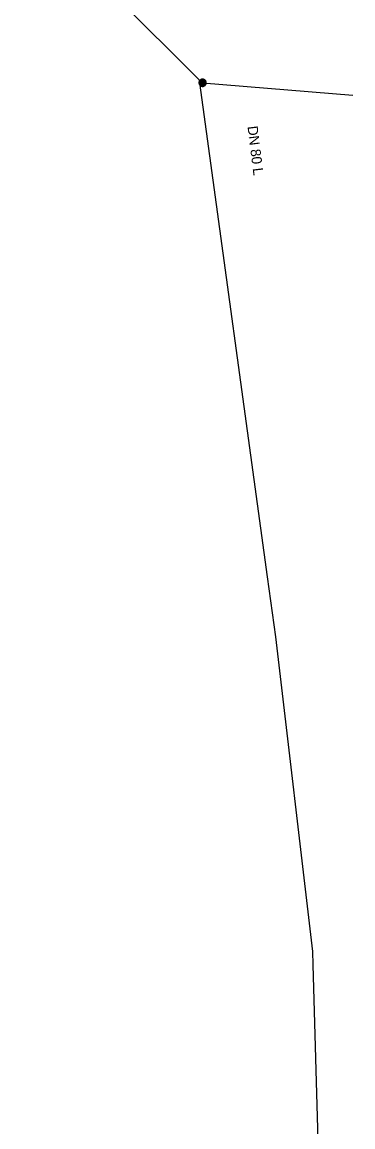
# Model space of a CAD drawing. Extents: x -818321 to -817653, y -1049725 to -1049329.
# Drawn here: x -818104.3 to -818081.5, y -1049527 to -1049450.7 of the extents above; entities that cross this region are included whole.
import ezdxf

# ---------------------------------------------------------------- set-up
doc = ezdxf.new("R2010")
doc.units = 0
doc.layers.add('Default', color=7, linetype='Continuous')
doc.layers.add('Level 0', color=7, linetype='Continuous')

msp = doc.modelspace()

# ---------------------------------------------------------------- linework, layer by layer
at = {"layer": 'Default'}
for points in [[(-818091.895, -1049454.663), (-818091.832, -1049454.663), (-818091.773, -1049454.695), (-818091.713, -1049454.727), (-818091.679, -1049454.787), (-818091.645, -1049454.848), (-818091.645, -1049454.913), (-818091.645, -1049454.978), (-818091.678, -1049455.037), (-818091.711, -1049455.097), (-818091.771, -1049455.13), (-818091.83, -1049455.163), (-818091.895, -1049455.163), (-818091.96, -1049455.163), (-818092.02, -1049455.13), (-818092.079, -1049455.097), (-818092.112, -1049455.037), (-818092.145, -1049454.978), (-818092.145, -1049454.913), (-818092.145, -1049454.848), (-818092.112, -1049454.787), (-818092.078, -1049454.727), (-818092.018, -1049454.695), (-818091.959, -1049454.663), (-818091.895, -1049454.663)], [(-818091.895, -1049454.686), (-818091.953, -1049454.686), (-818092.007, -1049454.715), (-818092.061, -1049454.745), (-818092.091, -1049454.799), (-818092.122, -1049454.854), (-818092.122, -1049454.913), (-818092.122, -1049454.972), (-818092.092, -1049455.026), (-818092.062, -1049455.08), (-818092.008, -1049455.11), (-818091.954, -1049455.139), (-818091.895, -1049455.139), (-818091.836, -1049455.139), (-818091.782, -1049455.11), (-818091.728, -1049455.08), (-818091.698, -1049455.026), (-818091.669, -1049454.972), (-818091.669, -1049454.913), (-818091.669, -1049454.854), (-818091.699, -1049454.799), (-818091.73, -1049454.745), (-818091.784, -1049454.715), (-818091.838, -1049454.686), (-818091.895, -1049454.686)], [(-818091.895, -1049454.703), (-818091.842, -1049454.703), (-818091.793, -1049454.73), (-818091.743, -1049454.757), (-818091.714, -1049454.808), (-818091.686, -1049454.858), (-818091.686, -1049454.913), (-818091.686, -1049454.968), (-818091.713, -1049455.017), (-818091.741, -1049455.067), (-818091.791, -1049455.095), (-818091.841, -1049455.122), (-818091.895, -1049455.122), (-818091.95, -1049455.122), (-818092, -1049455.095), (-818092.05, -1049455.067), (-818092.077, -1049455.017), (-818092.105, -1049454.968), (-818092.105, -1049454.913), (-818092.105, -1049454.858), (-818092.077, -1049454.808), (-818092.049, -1049454.757), (-818091.998, -1049454.73), (-818091.948, -1049454.703), (-818091.895, -1049454.703)], [(-818091.896, -1049454.725), (-818091.974, -1049454.725), (-818092.028, -1049454.78), (-818092.083, -1049454.835), (-818092.083, -1049454.913), (-818092.083, -1049454.991), (-818092.028, -1049455.046), (-818091.973, -1049455.1), (-818091.896, -1049455.1), (-818091.818, -1049455.1), (-818091.763, -1049455.046), (-818091.708, -1049454.991), (-818091.708, -1049454.913), (-818091.708, -1049454.835), (-818091.762, -1049454.78), (-818091.817, -1049454.725), (-818091.896, -1049454.725)], [(-818091.896, -1049454.748), (-818091.827, -1049454.748), (-818091.779, -1049454.796), (-818091.732, -1049454.844), (-818091.732, -1049454.912), (-818091.732, -1049454.98), (-818091.78, -1049455.028), (-818091.828, -1049455.076), (-818091.896, -1049455.076), (-818091.964, -1049455.076), (-818092.012, -1049455.028), (-818092.06, -1049454.98), (-818092.06, -1049454.912), (-818092.06, -1049454.844), (-818092.012, -1049454.796), (-818091.964, -1049454.748), (-818091.896, -1049454.748)], [(-818091.896, -1049454.768), (-818091.956, -1049454.768), (-818091.998, -1049454.81), (-818092.04, -1049454.853), (-818092.04, -1049454.912), (-818092.04, -1049454.972), (-818091.998, -1049455.014), (-818091.956, -1049455.057), (-818091.896, -1049455.057), (-818091.836, -1049455.057), (-818091.794, -1049455.014), (-818091.751, -1049454.972), (-818091.751, -1049454.912), (-818091.751, -1049454.853), (-818091.793, -1049454.81), (-818091.835, -1049454.768), (-818091.896, -1049454.768)], [(-818091.895, -1049454.788), (-818091.843, -1049454.788), (-818091.807, -1049454.824), (-818091.77, -1049454.861), (-818091.77, -1049454.913), (-818091.77, -1049454.965), (-818091.807, -1049455.001), (-818091.843, -1049455.038), (-818091.895, -1049455.038), (-818091.947, -1049455.038), (-818091.984, -1049455.001), (-818092.02, -1049454.965), (-818092.02, -1049454.913), (-818092.02, -1049454.861), (-818091.984, -1049454.824), (-818091.948, -1049454.788), (-818091.895, -1049454.788)], [(-818091.895, -1049454.811), (-818091.938, -1049454.811), (-818091.967, -1049454.841), (-818091.997, -1049454.87), (-818091.997, -1049454.913), (-818091.997, -1049454.955), (-818091.967, -1049454.985), (-818091.938, -1049455.014), (-818091.895, -1049455.014), (-818091.853, -1049455.014), (-818091.824, -1049454.985), (-818091.794, -1049454.955), (-818091.794, -1049454.913), (-818091.794, -1049454.87), (-818091.824, -1049454.841), (-818091.853, -1049454.811), (-818091.895, -1049454.811)], [(-818091.895, -1049454.828), (-818091.86, -1049454.828), (-818091.836, -1049454.853), (-818091.811, -1049454.877), (-818091.811, -1049454.913), (-818091.811, -1049454.948), (-818091.836, -1049454.972), (-818091.861, -1049454.997), (-818091.895, -1049454.997), (-818091.931, -1049454.997), (-818091.955, -1049454.972), (-818091.98, -1049454.948), (-818091.98, -1049454.913), (-818091.98, -1049454.877), (-818091.955, -1049454.853), (-818091.931, -1049454.828), (-818091.895, -1049454.828)], [(-818091.895, -1049454.85), (-818091.921, -1049454.85), (-818091.94, -1049454.869), (-818091.958, -1049454.887), (-818091.958, -1049454.913), (-818091.958, -1049454.939), (-818091.939, -1049454.957), (-818091.921, -1049454.975), (-818091.895, -1049454.975), (-818091.869, -1049454.975), (-818091.851, -1049454.957), (-818091.833, -1049454.939), (-818091.833, -1049454.913), (-818091.833, -1049454.887), (-818091.851, -1049454.869), (-818091.869, -1049454.85), (-818091.895, -1049454.85)], [(-818091.895, -1049454.874), (-818091.879, -1049454.874), (-818091.868, -1049454.885), (-818091.856, -1049454.896), (-818091.856, -1049454.913), (-818091.856, -1049454.929), (-818091.868, -1049454.94), (-818091.879, -1049454.952), (-818091.895, -1049454.952), (-818091.912, -1049454.952), (-818091.923, -1049454.94), (-818091.935, -1049454.929), (-818091.935, -1049454.913), (-818091.935, -1049454.896), (-818091.923, -1049454.885), (-818091.912, -1049454.874), (-818091.895, -1049454.874)], [(-818091.895, -1049454.889), (-818091.905, -1049454.889), (-818091.912, -1049454.896), (-818091.919, -1049454.903), (-818091.919, -1049454.913), (-818091.919, -1049454.923), (-818091.912, -1049454.929), (-818091.905, -1049454.936), (-818091.895, -1049454.936), (-818091.885, -1049454.936), (-818091.879, -1049454.929), (-818091.872, -1049454.923), (-818091.872, -1049454.913), (-818091.872, -1049454.903), (-818091.879, -1049454.896), (-818091.885, -1049454.889), (-818091.895, -1049454.889)]]:
    msp.add_open_spline(points, degree=3, dxfattribs=at)
at = {"layer": 'Level 0'}
for p, q in [((-818104.333, -1049442.508), (-818092.141, -1049454.717)), ((-818092.141, -1049454.717), (-818092.119, -1049454.913)), ((-818092.119, -1049454.913), (-818087.437, -1049489.009)), ((-818092.119, -1049454.913), (-818091.895, -1049454.913)), ((-818091.895, -1049454.913), (-818081.538, -1049455.76)), ((-818087.437, -1049489.009), (-818086.868, -1049493.15)), ((-818086.868, -1049493.15), (-818084.324, -1049514.864)), ((-818084.324, -1049514.864), (-818084.297, -1049515.783)), ((-818084.297, -1049515.783), (-818083.68, -1049536.893))]:
    msp.add_line(p, q, dxfattribs=at)

# ---------------------------------------------------------------- texts
msp.add_text('DN 80 L', height=0.7, rotation=277, dxfattribs=at).set_placement((-818088.802, -1049457.932))

doc.saveas('drawing.dxf')
